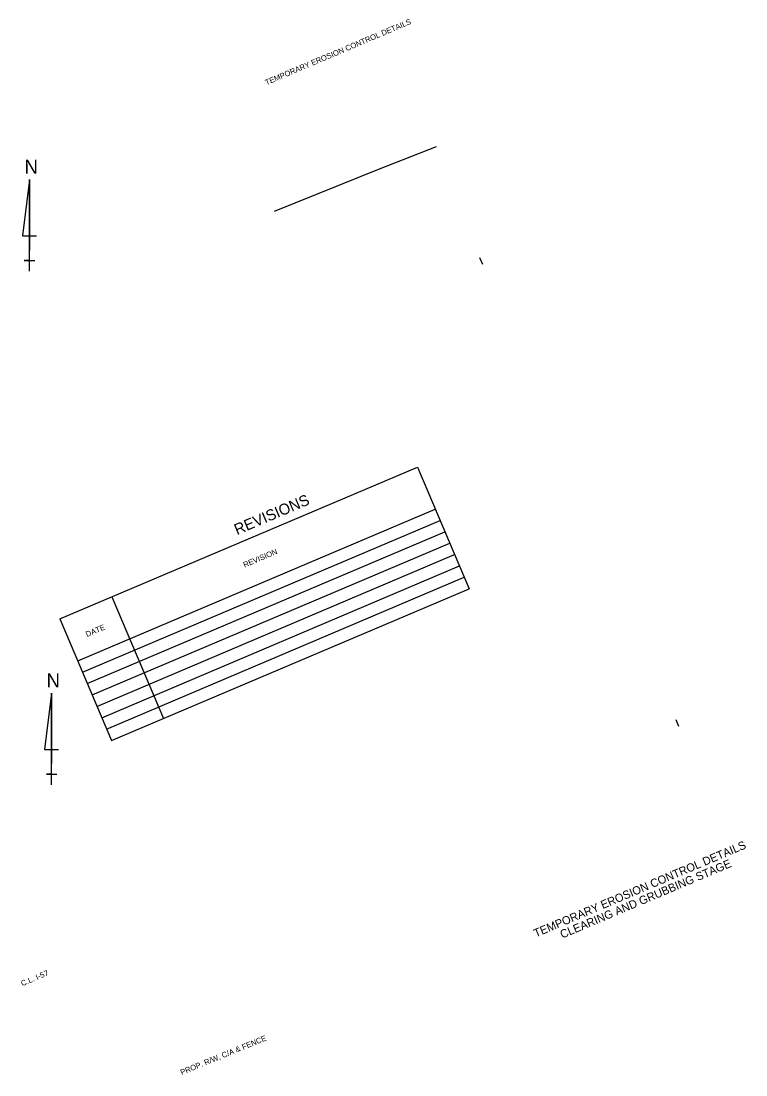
# Model space of a CAD drawing. Extents: x 1718863 to 1720683, y 766511 to 767857.
# Drawn here: x 1719890 to 1720683, y 766704 to 767857 of the extents above; entities that cross this region are included whole.
import ezdxf

# ---------------------------------------------------------------- set-up
doc = ezdxf.new("R2010")
doc.units = 0
for name, color, linetype in [('63', 7, 'Continuous'), ('Default', 7, 'Continuous'), ('EC_STG1_SILT FENCE', 7, 'Continuous'), ('G-ANNO-TEXT', 7, 'Continuous'), ('R_Draft', 7, 'Continuous')]:
    doc.layers.add(name, color=color, linetype=linetype)

msp = doc.modelspace()

# ---------------------------------------------------------------- linework, layer by layer
at = {"layer": '63'}
for p, q in [((1719899.6, 767683.2), (1719891.9, 767621.6)), ((1719899.6, 767583.2), (1719899.6, 767683.2)), ((1719899.6, 767683.2), (1719899.6, 767606.2)), ((1719891.9, 767621.6), (1719907.3, 767621.6)), ((1719899.6, 767583.2), (1719899.6, 767606.2)), ((1719899.6, 767594.7), (1719893.8, 767594.7)), ((1719893.8, 767594.7), (1719905.4, 767594.7)), ((1719899.6, 767583.2), (1719899.6, 767594.7)), ((1719923.8, 767121.3), (1719916.1, 767059.8)), ((1719923.8, 767021.3), (1719923.8, 767121.3)), ((1719923.8, 767121.3), (1719923.8, 767044.4)), ((1719916.1, 767059.8), (1719931.4, 767059.8)), ((1719923.8, 767021.3), (1719923.8, 767044.4)), ((1719923.8, 767032.9), (1719918, 767032.9)), ((1719918, 767032.9), (1719929.5, 767032.9)), ((1719923.8, 767021.3), (1719923.8, 767032.9))]:
    msp.add_line(p, q, dxfattribs=at)
at = {"layer": 'Default'}
for p, q in [((1720395.5, 767590.3), (1720392.4, 767597.7)), ((1719932.7, 767202.8), (1720324, 767368.8)), ((1720324, 767368.8), (1720380.4, 767235.7)), ((1719952.3, 767156.8), (1720343.5, 767322.7)), ((1719957.5, 767144.3), (1720348.8, 767310.3)), ((1719962.8, 767131.9), (1720354.1, 767297.9)), ((1719968.1, 767119.5), (1720359.3, 767285.5)), ((1719968.1, 767119.5), (1720359.3, 767285.5)), ((1719973.4, 767107), (1720364.6, 767273)), ((1719978.6, 767094.6), (1720369.9, 767260.6)), ((1719983.9, 767082.2), (1720375.1, 767248.2)), ((1719989.2, 767069.8), (1720380.4, 767235.7)), ((1719989.6, 767226.9), (1720046.1, 767093.9)), ((1719932.7, 767202.8), (1719989.2, 767069.8)), ((1720606.5, 767092.8), (1720609.6, 767085.4))]:
    msp.add_line(p, q, dxfattribs=at)
at = {"layer": 'EC_STG1_SILT FENCE'}
msp.add_lwpolyline([(1720167.6, 767648.7), (1720280.5, 767694.3), (1720344.7, 767719.4)], dxfattribs=at)

# ---------------------------------------------------------------- texts
at = {"layer": '63'}
for p in [(1719894, 767689.6), (1719918.1, 767127.7)]:
    msp.add_text('N', height=15.4, rotation=360, dxfattribs=at).set_placement(p)
at = {"layer": 'Default'}
for s, height, p in [('REVISIONS', 12, (1720126.6, 767294.3)), ('REVISION', 6, (1720134.9, 767258.7)), ('DATE', 6, (1719962.5, 767182.8))]:
    msp.add_text(s, height=height, rotation=22.9899, dxfattribs=at).set_placement(p)
at = {"layer": 'G-ANNO-TEXT'}
for s, height, p in [('TEMPORARY EROSION CONTROL DETAILS', 6, (1720158.8, 767786.4)), ('TEMPORARY EROSION CONTROL DETAILS', 9, (1720453.5, 766854.1)), ('CLEARING AND GRUBBING STAGE', 9, (1720482.4, 766852.9))]:
    msp.add_text(s, height=height, rotation=22.9899, dxfattribs=at).set_placement(p)
at = {"layer": 'R_Draft'}
for s, rotation, p in [('C.L. I-57', 23, (1719891.7, 766800.8)), ('PROP. R/W, C/A & FENCE', 22.2954, (1720066.1, 766703.6))]:
    msp.add_text(s, height=6, rotation=rotation, dxfattribs=at).set_placement(p)

doc.saveas('drawing.dxf')
